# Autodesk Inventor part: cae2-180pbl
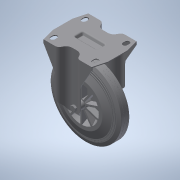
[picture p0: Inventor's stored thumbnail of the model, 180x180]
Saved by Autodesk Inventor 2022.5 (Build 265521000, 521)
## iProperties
Created: 2016-12
Part Number: cae2-180pbl
Material: 一般
Document SubType Name: Modeling
Designer: imaocorp
Density: 1 g/cm^3
Appearance: 既定
Author: imaocorp
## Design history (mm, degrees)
node "cae2-180pbl.x_t1"
node "RE_E2_180_PBL_1HIHI"
node "Base1"
